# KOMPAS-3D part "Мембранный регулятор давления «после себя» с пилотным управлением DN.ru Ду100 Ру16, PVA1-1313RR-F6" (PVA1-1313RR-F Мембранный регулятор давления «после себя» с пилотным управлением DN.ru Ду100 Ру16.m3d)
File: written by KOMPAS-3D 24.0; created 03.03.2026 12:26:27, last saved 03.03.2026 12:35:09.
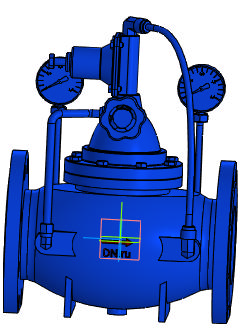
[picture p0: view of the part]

Document properties: Автор: R2D2; Полное имя файла: PVA1-1313RR-F6 Мембранный регулятор давления «после себя» с пилотным управлением DN.ru Ду100 Ру16.cdw

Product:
- Part/product: Мембранный регулятор давления «после себя» с пилотным управлением DN.ru Ду100 Ру16  | designation PVA1-1313RR-F6
    Масса: 18
    Раздел спецификации: Прочие изделия
    Форматы листов документа: A3
    Примечание: D230-10620
    additional columns: D230-10620

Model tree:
1. Операция без истории:2

Expressions: PVA1-1313RR-F6
Referenced files in C:\Program Files\ASCON\KOMPAS-3D v24\Libs\EasySteel\: Rolled metal.kle, StandartSolutions.kle, DSTVProperties.lpt
Referenced files in C:\Program Files\ASCON\KOMPAS-3D v24\Templates\: Констр. чертеж А3 гориз. перв. лист.cdt
Referenced files in C:\Program Files\ASCON\KOMPAS-3D v24\Libs\EasySteel\BeltEndings\: 
Referenced files in C:\Program Files\ASCON\KOMPAS-3D v24\Libs\EasySteel\Punctures\: 
Referenced files in C:\Program Files\ASCON\KOMPAS-3D v24\Libs\EasySteel\Insulations\: 
Referenced files in C:\Program Files\ASCON\KOMPAS-3D v24\Libs\Pipeline\: StylesTemplate.a3d, TemplateHPH, InsulationStylesTemplate.a3d, Insulation
Referenced files in E:\Работа\Зайцев\PVA1-1313RR-F Мембранный регулятор давления «после себя» с пилотным управлением DN.ru Ду50-200 Ру16\DN100\исходные материалы\: 
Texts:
  Уголок равнополочный по ГОСТ 8509-93 (Спец)
  config2DpacketName
  config2DstdSizeID
  Констр. чертеж А3 гориз. перв. лист.cdt
  Болт ГОСТ 22353-77
  Шайба ГОСТ 22355-77
  Гайка ГОСТ 22354-77
  Нормальная пружинная шайба ГОСТ 6402-70 (исп. 1)
  SeaRox SL 436
  Отводы ГОСТ 17375-2001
